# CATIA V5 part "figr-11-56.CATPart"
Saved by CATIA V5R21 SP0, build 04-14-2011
Part number: Part1
Bounding box of the stored display mesh (mm): x -50 to 50, y -100 to 150, z -20 to 50
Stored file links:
  D:\CATIA V5R21 E-RESOURCES\CATIA-V5R21\catia-v5r21-prt\c11-catia-v5r21-prt\c11-catia-v5r21-figr-11-56.CATPart
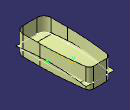
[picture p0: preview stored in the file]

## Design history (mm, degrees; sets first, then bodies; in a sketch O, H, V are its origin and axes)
Set1
  Extrude1: Element1 Sketch2, Lim1 50, Lim2 50, Direction yz-plane
  Sketch1 on xy-plane, origin (0, 0, 0), H (1, 0, 0), V (0, 1, 0)
    arc A1 centre (25, -75) radius 25 from (25, -100) to (50, -75) ccw
    line L1 (50, -75) -> (50, -15)
    point P4 (50, -15)
    arc A2 centre (-950, -15) radius 1000 from (50, -15) to (38.3367, 137.2843) ccw
    line L2 (23.5117, 150) -> (-23.5117, 150)
    line L3 (25, -100) -> (-25, -100)
    arc A3 centre (-25, -75) radius 25 from (-25, -100) to (-50, -75) cw
    line L4 (-50, -75) -> (-50, -15)
    point P9 (-50, -15)
    arc A4 centre (950, -15) radius 1000 from (-50, -15) to (-38.3367, 137.2843) cw
    reference projected line E1 (-50, -100) -> (50, -100) from edge of Extrude1
    axis line L5 (0, 170.4214) -> (0, -120.6595)
    point P11 (0, 170.4214)
    reference projected line E2 (50, -70) -> (50, 129.9971) from edge of Extrude1
    reference projected line E3 (-50, 129.9971) -> (-50, -70) from edge of Extrude1
    reference projected line E4 (-50, -100) -> (50, -100) from edge of Extrude1
    reference projected line E5 (50, 150) -> (-50, 150) from edge of Extrude1
    arc A5 centre (-23.5117, 135) radius 15 from (-38.3367, 137.2843) to (-23.5117, 150) cw
    arc A6 centre (23.5117, 135) radius 15 from (38.3367, 137.2843) to (23.5117, 150) ccw
    distance E4 P4 = 85
    radius A2 = 1000
    radius A5 = 15
    radius A6 = 15
    radius A1 = 25
    radius A3 = 25
    radius A4 = 1000
    tangency: L1 A1, A2 L1, L3 A1, A3 L3, A4 L4, L5 A3, A5 L2, A5 A4, A6 A2, A6 L2, A3 L4
    horizontal: L2 H
    coincidence: L3 E1, P11 V, L1 E2, L4 E3, L2 E5
    symmetry: P4 P9 L5
  Extrude2: Element1 Sketch1, Lim1 50, Lim2 20, Direction xy-plane
Body1 (main body)
  Sketch2 on yz-plane, origin (0, 0, 0), H (0, 1, 0), V (0, 0, 1)
    point P1 (-100, 0)
    line L1 (-100, 0) -> (-70, 3.8724)
    point P2 (-70, 3.8724)
    arc A1 centre (26.0141, -739.9564) radius 750 from (-70, 3.8724) to (129.9971, 2.8003) cw
    point P4 (129.9971, 2.8003)
    line L2 (129.9971, 2.8003) -> (150, 0)
    point P5 (150, 0)
    distance P1 P5 = 250
    distance P1 O = 100
    radius A1 = 750
    distance P2 P4 = 200
    distance P2 V = 70
    coincidence: P1 H, P5 H
    tangency: A1 L1, L2 A1
  ThickSurface1: BotOffset 0, Surface Extrude1, TopOffset 5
